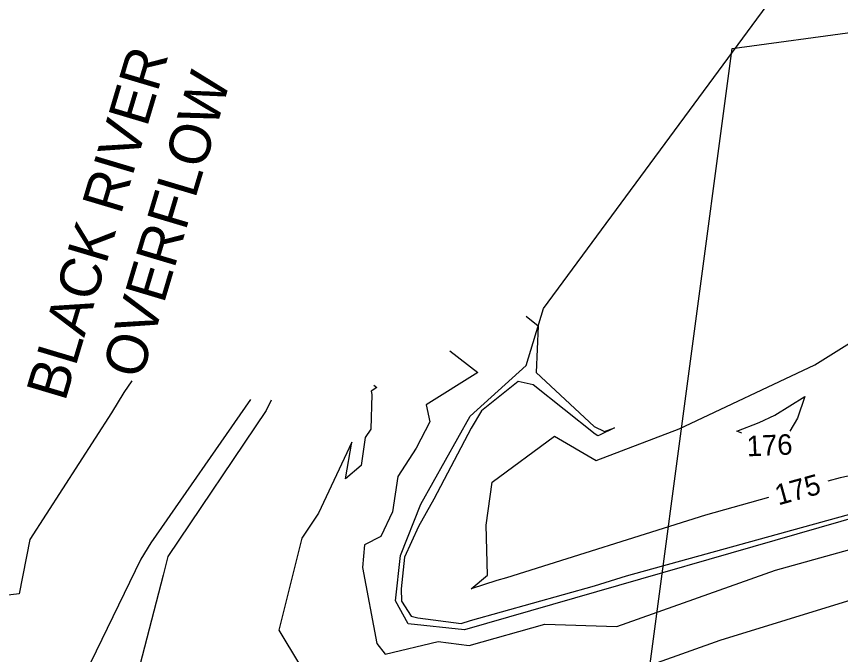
# Model space of a CAD drawing. Extents: x 2086416 to 2115205, y 575507 to 632762.
# Drawn here: x 2112066 to 2112146.4, y 581789.8 to 581852.1 of the extents above; entities that cross this region are included whole.
import ezdxf

# ---------------------------------------------------------------- set-up
doc = ezdxf.new("R2010")
doc.units = 0
for name, color, linetype in [('DTM Contours Major', 7, 'Continuous'), ('DTM Contours Major Text', 7, 'Continuous'), ('DTM Contours Minor', 7, 'Continuous'), ('DTM Contours Minor Text', 7, 'Continuous'), ('Exist Hydro Stream or Body of Water', 7, 'Continuous'), ('Exist Hydro Stream or Body of Water Text', 7, 'Continuous'), ('Prop Horizontal Alignment Station Label', 7, 'Continuous')]:
    doc.layers.add(name, color=color, linetype=linetype)

msp = doc.modelspace()

# ---------------------------------------------------------------- linework, layer by layer
at = {"layer": 'DTM Contours Major'}
for points in [[(2112112.852, 581797.036), (2112110.373, 581796.216), (2112111.939, 581797.574), (2112111.828, 581802.432), (2112112.403, 581806.655), (2112118.493, 581811.142), (2112122.542, 581808.758), (2112130.659, 581811.838), (2112143.864, 581818.08), (2112150.131, 581821.978), (2112154.41, 581825.323), (2112162.026, 581851.087), (2112170.706, 581844.388)], [(2112175.456, 581840.722), (2112175.769, 581840.48), (2112193.694, 581829.274), (2112195.276, 581829.692), (2112195.047, 581827.156), (2112196.622, 581818.044), (2112195.366, 581817.87), (2112191.903, 581817.272), (2112191.458, 581826.23), (2112164.651, 581815.306), (2112160.701, 581810.905), (2112152.677, 581809.75), (2112150.218, 581807.862), (2112146.336, 581807.068), (2112145.128, 581806.734)], [(2112139.345, 581805.134), (2112133.199, 581803.432), (2112113.809, 581797.303), (2112112.852, 581797.036)]]:
    msp.add_lwpolyline(points, dxfattribs=at)
at = {"layer": 'DTM Contours Minor'}
for points in [[(2112115.713, 581822.826), (2112116.897, 581821.903), (2112116.712, 581817.349), (2112122.363, 581812.07), (2112123.367, 581811.585), (2112124.351, 581811.928), (2112122.864, 581811.224), (2112122.728, 581811.173), (2112122.462, 581811.329), (2112116.413, 581816.131), (2112114.958, 581816.449), (2112111.37, 581813.594), (2112110.359, 581811.895), (2112106.726, 581804.974), (2112105.219, 581802.328), (2112103.86, 581799.307), (2112103.546, 581796.229), (2112103.563, 581795.027), (2112104.514, 581793.569), (2112105.146, 581793.388), (2112109.379, 581792.84), (2112110.293, 581793.142), (2112122.385, 581796.513), (2112125.495, 581797.496), (2112152.231, 581804.896)], [(2112108.287, 581819.458), (2112111.018, 581817.331), (2112105.99, 581814.171), (2112106.323, 581812.513), (2112105.005, 581809.956), (2112103.203, 581807.204), (2112102.687, 581803.732), (2112101.566, 581801.335), (2112099.948, 581800.537), (2112099.75, 581798.317), (2112101.168, 581790.89), (2112101.983, 581789.868), (2112107.129, 581791.075), (2112110.158, 581790.699), (2112117.544, 581792.779), (2112124.569, 581792.568), (2112140.053, 581798.053), (2112152.795, 581801.594)], [(2112077.285, 581816.541), (2112076.491, 581815.398), (2112075.281, 581813.414), (2112067.316, 581801.053), (2112066.275, 581795.739), (2112047.998, 581793.548)], [(2112100.861, 581816.09), (2112101.15, 581815.866), (2112100.619, 581815.532), (2112100.686, 581815.199), (2112100.566, 581811.801), (2112100.038, 581810.996), (2112099.635, 581808.281), (2112098.112, 581806.98), (2112098.734, 581810.558), (2112095.483, 581803.62), (2112093.836, 581801.177), (2112091.592, 581792.199), (2112095.525, 581785.642)], [(2112138.455, 581812.451), (2112139.964, 581813.164), (2112142.912, 581814.998), (2112142.175, 581812.89), (2112141.427, 581811.62)], [(2112088.832, 581814.717), (2112079.117, 581800.733), (2112078.139, 581799.131), (2112071.052, 581784.529), (2112066.895, 581774.978), (2112066.081, 581772.081), (2112065.416, 581771.202), (2112065.876, 581771.198), (2112064.244, 581767.513), (2112055.948, 581749.212), (2112056.111, 581747.536), (2112056.41, 581741.807), (2112056.854, 581736.905), (2112057.524, 581734.784), (2112059.14, 581725.01)], [(2112090.867, 581814.656), (2112090.381, 581813.617), (2112080.779, 581799.37), (2112080.326, 581797.56), (2112075.592, 581779.241), (2112073.887, 581776.041), (2112083.954, 581769.103), (2112085.39, 581767.315), (2112092.199, 581754.098), (2112096.773, 581742.846), (2112096.783, 581742.376), (2112097.229, 581741.374), (2112099.723, 581728.458), (2112099.682, 581727.468)], [(2112136.745, 581811.422), (2112136.273, 581811.623), (2112138.455, 581812.451)], [(2112153.005, 581789.685), (2112135.416, 581787.2), (2112127.574, 581785.689), (2112124.665, 581785.159), (2112123.771, 581785.177), (2112111.094, 581783.733), (2112111.035, 581783.781), (2112109.405, 581784.144), (2112111.049, 581784.24), (2112117.074, 581788.124), (2112125.244, 581787.878), (2112134.648, 581791.209), (2112153.514, 581797.044), (2112157.376, 581796.211), (2112168.643, 581796.696), (2112174.716, 581797.127), (2112198.243, 581802.384), (2112199.855, 581802.612), (2112215.462, 581799.046), (2112243.201, 581806.994), (2112245.026, 581807.254), (2112246.641, 581807.449), (2112260.422, 581806.872)]]:
    msp.add_lwpolyline(points, dxfattribs=at)
at = {"layer": 'Exist Hydro Stream or Body of Water'}
for points in [[(2112117.413, 581823.597), (2112152.012, 581870.552), (2112152.346, 581889.353), (2112159.732, 581907.409), (2112163.614, 581922.716), (2112164.824, 581936.954), (2112168.079, 581951.98)], [(2112300.064, 581820.898), (2112244.202, 581814.187), (2112196.821, 581807.522), (2112152.85, 581804.668), (2112109.697, 581792.235), (2112104.209, 581792.801), (2112102.974, 581795.071), (2112103.482, 581799.485), (2112105.456, 581804.504), (2112110.255, 581813.09), (2112115.716, 581818.028), (2112117.413, 581823.597)]]:
    msp.add_lwpolyline(points, dxfattribs=at)
at = {"layer": 'Prop Horizontal Alignment Station Label'}
for p, q in [((2112135.809, 581848.952), (2112267.874, 581866.974)), ((2112120.307, 581732.422), (2112135.809, 581848.952))]:
    msp.add_line(p, q, dxfattribs=at)

# ---------------------------------------------------------------- texts
at = {"layer": 'DTM Contours Major Text'}
msp.add_text('175', height=2, rotation=15.47125, dxfattribs=at).set_placement((2112140.31, 581804.363))
at = {"layer": 'DTM Contours Minor Text'}
msp.add_text('176', height=2, rotation=2.42056, dxfattribs=at).set_placement((2112137.274, 581809.152))
at = {"layer": 'Exist Hydro Stream or Body of Water Text'}
for s, p in [('BLACK RIVER', (2112070.755, 581814.425)), ('OVERFLOW', (2112078.176, 581816.565))]:
    msp.add_text(s, height=4, rotation=73.39328, dxfattribs=at).set_placement(p)

doc.saveas('drawing.dxf')
